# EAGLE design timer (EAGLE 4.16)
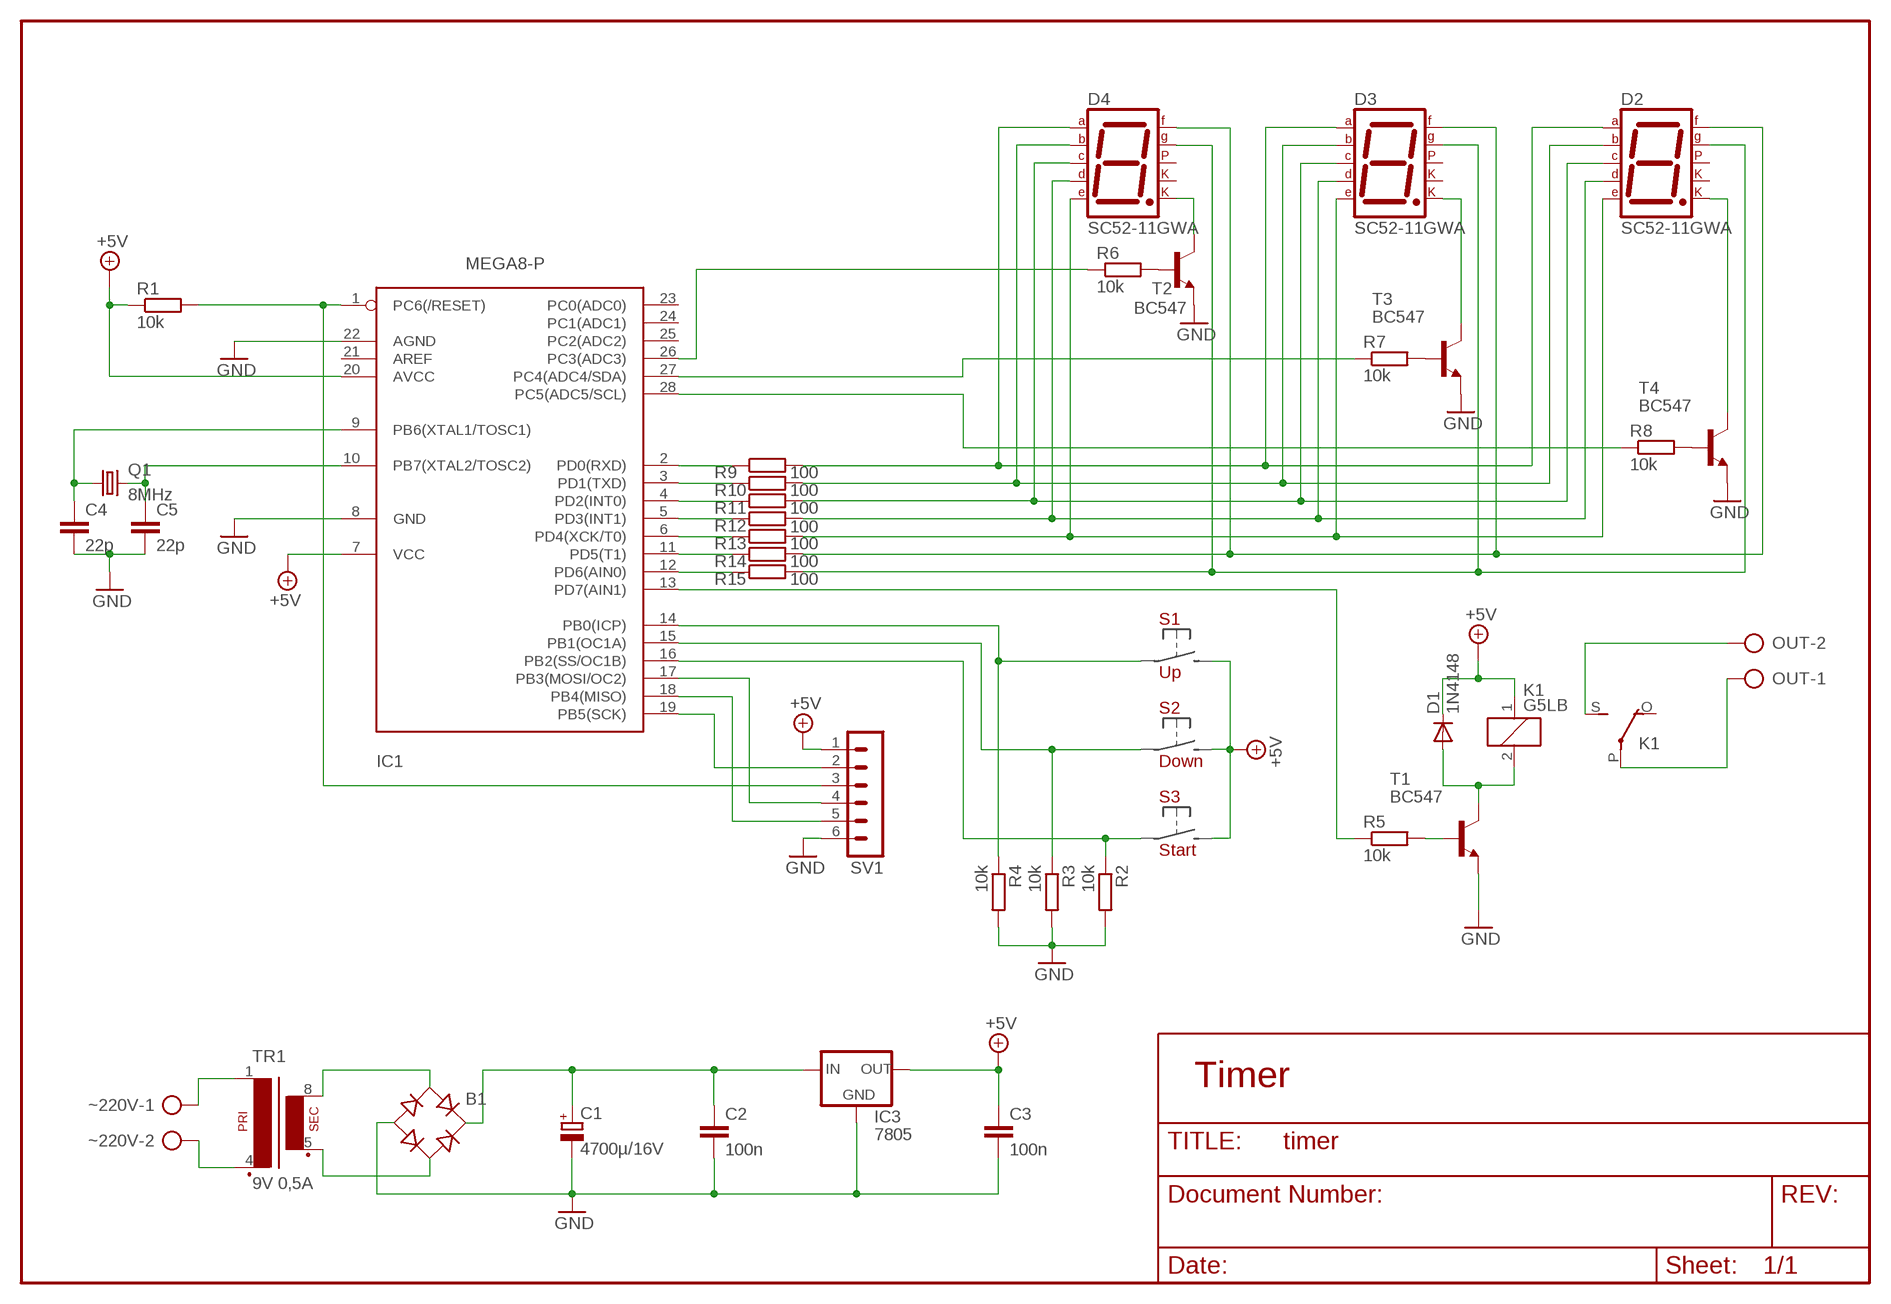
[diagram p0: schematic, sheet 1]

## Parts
B1  RB1A  [RB1A]
C1  4700µ/16V  CPOL-EUE7.5-16  [E7,5-16]
C2  100n  C-EU050-025X075  [C050-025X075]
C3  100n  C-EU050-025X075  [C050-025X075]
C4  22p  C-EU025-025X050  [C025-025X050]
C5  22p  C-EU025-025X050  [C025-025X050]
D1  1N4148  [DO35-10]
D2  SC52-11GWA  7SEG-CK  [7SEG-13]
D3  SC52-11GWA  7SEG-CK  [7SEG-13]
D4  SC52-11GWA  7SEG-CK  [7SEG-13]
IC1  MEGA8-P  [DIL28-3]
IC3  7805  78XXS  [78XXS]
K1  G5LB  G5L  [G5LE]
OUT  AK500/2  [AK500/2]
Q1  8MHz  CRYTALHC49U-V  [HC49U-V]
R1  10k  R-EU_0207/10  [0207/10]
R2  10k  R-EU_0207/10  [0207/10]
R3  10k  R-EU_0207/10  [0207/10]
R4  10k  R-EU_0207/10  [0207/10]
R5  10k  R-EU_0207/10  [0207/10]
R6  10k  R-EU_0207/10  [0207/10]
R7  10k  R-EU_0207/10  [0207/10]
R8  10k  R-EU_0207/10  [0207/10]
R9  100  R-EU_0207/10  [0207/10]
R10  100  R-EU_0207/10  [0207/10]
R11  100  R-EU_0207/10  [0207/10]
R12  100  R-EU_0207/10  [0207/10]
R13  100  R-EU_0207/10  [0207/10]
R14  100  R-EU_0207/10  [0207/10]
R15  100  R-EU_0207/10  [0207/10]
S1  Up  TASTER  [KEY]
S2  Down  TASTER  [KEY]
S3  Start  TASTER  [KEY]
SV1  MA06-1  [MA06-1]
T1  BC547  [TO92]
T2  BC547  [TO92]
T3  BC547  [TO92]
T4  BC547  [TO92]
TR1  9V 0,5A  TR  [TR]
~220V  AK500/2  [AK500/2]

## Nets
+5V: C3.1 D1.C IC1.7(VCC) IC1.20(AVCC) IC3.OUT K1.1 R1.1 S1.2 S2.2 S3.2 SV1.1
GND: B1.- C1.- C2.2 C3.2 C4.2 C5.2 IC1.8(GND) IC1.22(AGND) IC3.GND R2.2 R3.2 R4.2 SV1.6 T1.1(E) T2.1(E) T3.1(E) T4.1(E)
N$1: TR1.1 ~220V.1
N$2: TR1.4 ~220V.2
N$3: B1.AC1 TR1.8
N$4: B1.AC2 TR1.5
N$5: C4.1 IC1.9(PB6(XTAL1/TOSC1)) Q1.1
N$6: B1.+ C1.+ C2.1 IC3.IN
N$7: C5.1 IC1.10(PB7(XTAL2/TOSC2)) Q1.2
N$8: IC1.1(PC6(/RESET)) R1.2 SV1.3
N$9: D2.7(A) D3.7(A) D4.7(A) R9.2
N$10: IC1.19(PB5(SCK)) SV1.2
N$11: IC1.17(PB3(MOSI/OC2)) SV1.4
N$12: IC1.18(PB4(MISO)) SV1.5
N$13: D2.6(B) D3.6(B) D4.6(B) R10.2
N$14: D2.4(C) D3.4(C) D4.4(C) R11.2
N$15: D2.2(D) D3.2(D) D4.2(D) R12.2
N$16: D2.1(E) D3.1(E) D4.1(E) R13.2
N$17: D2.10(G) D3.10(G) D4.10(G) R15.2
N$18: D2.9(F) D3.9(F) D4.9(F) R14.2
N$19: R6.2 T2.2(B)
N$20: R7.2 T3.2(B)
N$21: R8.2 T4.2(B)
N$26: IC1.14(PB0(ICP)) R4.1 S1.1
N$27: IC1.15(PB1(OC1A)) R3.1 S2.1
N$28: IC1.16(PB2(SS/OC1B)) R2.1 S3.1
N$29: K1.S(2:S) OUT.2
N$30: K1.P(2:P) OUT.1
N$31: IC1.13(PD7(AIN1)) R5.1
N$32: R5.2 T1.2(B)
N$33: D1.A K1.2 T1.3(C)
N$59: D4.8(CK2) T2.3(C)
N$60: D3.8(CK2) T3.3(C)
N$61: D2.8(CK2) T4.3(C)
N$62: IC1.26(PC3(ADC3)) R6.1
N$63: IC1.27(PC4(ADC4/SDA)) R7.1
N$64: IC1.28(PC5(ADC5/SCL)) R8.1
N$65: IC1.2(PD0(RXD)) R9.1
N$66: IC1.3(PD1(TXD)) R10.1
N$67: IC1.4(PD2(INT0)) R11.1
N$68: IC1.5(PD3(INT1)) R12.1
N$69: IC1.6(PD4(XCK/T0)) R13.1
N$70: IC1.11(PD5(T1)) R14.1
N$71: IC1.12(PD6(AIN0)) R15.1
Unconnected: D2.3(CK1) D2.5(DP) D3.3(CK1) D3.5(DP) D4.3(CK1) D4.5(DP) IC1.21(AREF) IC1.23(PC0(ADC0)) IC1.24(PC1(ADC1)) IC1.25(PC2(ADC2)) K1.O(2:O)

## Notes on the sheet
- Timer

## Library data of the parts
B1 = rectifier:RB1A: RECTIFIER 1 A
C1 = rcl:CPOL-EU: POLARIZED CAPACITOR, European symbol
C2-C5 = rcl:C-EU: CAPACITOR, European symbol
D1 = diode:1N4148: DIODE
D2-D4 = special:7SEG-CK: 7-segment DISPLAY single cathode, 13 mm
IC1 = atmel:MEGA8-P: MICROCONTROLLER 8 Kbytes FLASH 1 kbytes SRAM 512 bytes EEPROM USART 4-channel 10 bit ADC 2-channel 8 bit ADC Source: avr.lbr
IC3 = v-reg:78XXS: VOLTAGE REGULATOR
K1 = relay:G5L: RELAY 1 x switch, 10 A/120 V AC, 8 A/30 V ADC, Omron
OUT ~220V = con-ptr500:AK500/2: CONNECTOR
Q1 = crystal:CRYTAL: CRYSTAL
R1-R15 = rcl:R-EU_: RESISTOR, European symbol
S1-S3 = 0_my_lib:TASTER
SV1 = con-lstb:MA06-1: PIN HEADER
T1-T4 = transistor:BC547: NPN TRANSISTOR
TR1 = 0_my_lib:TR

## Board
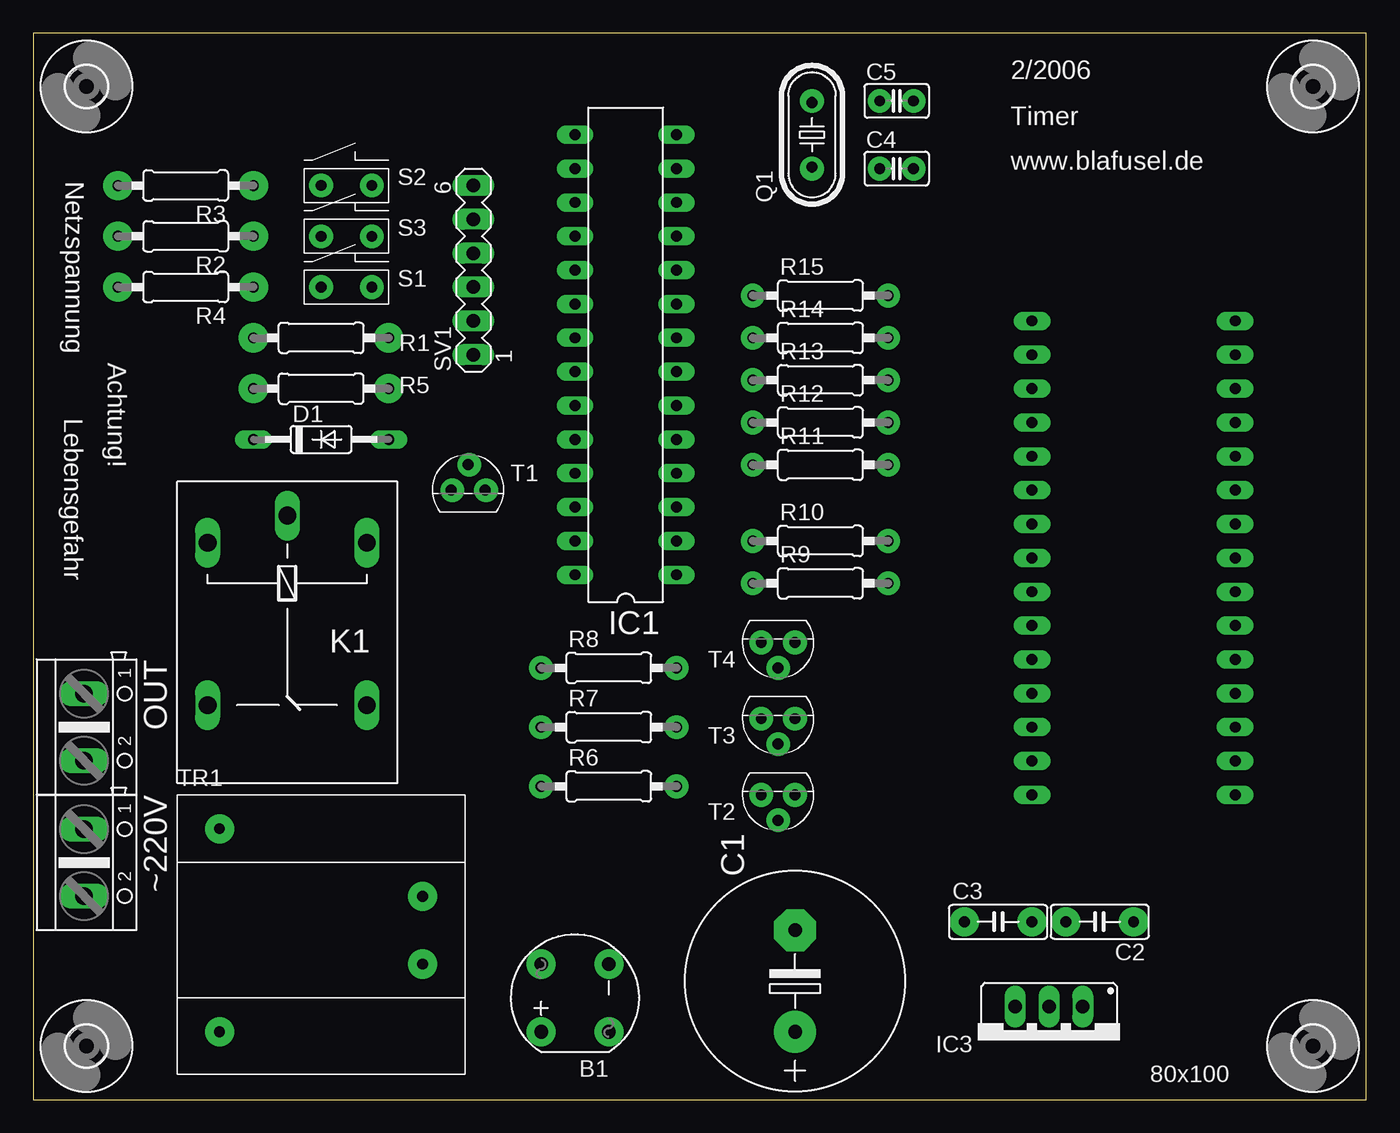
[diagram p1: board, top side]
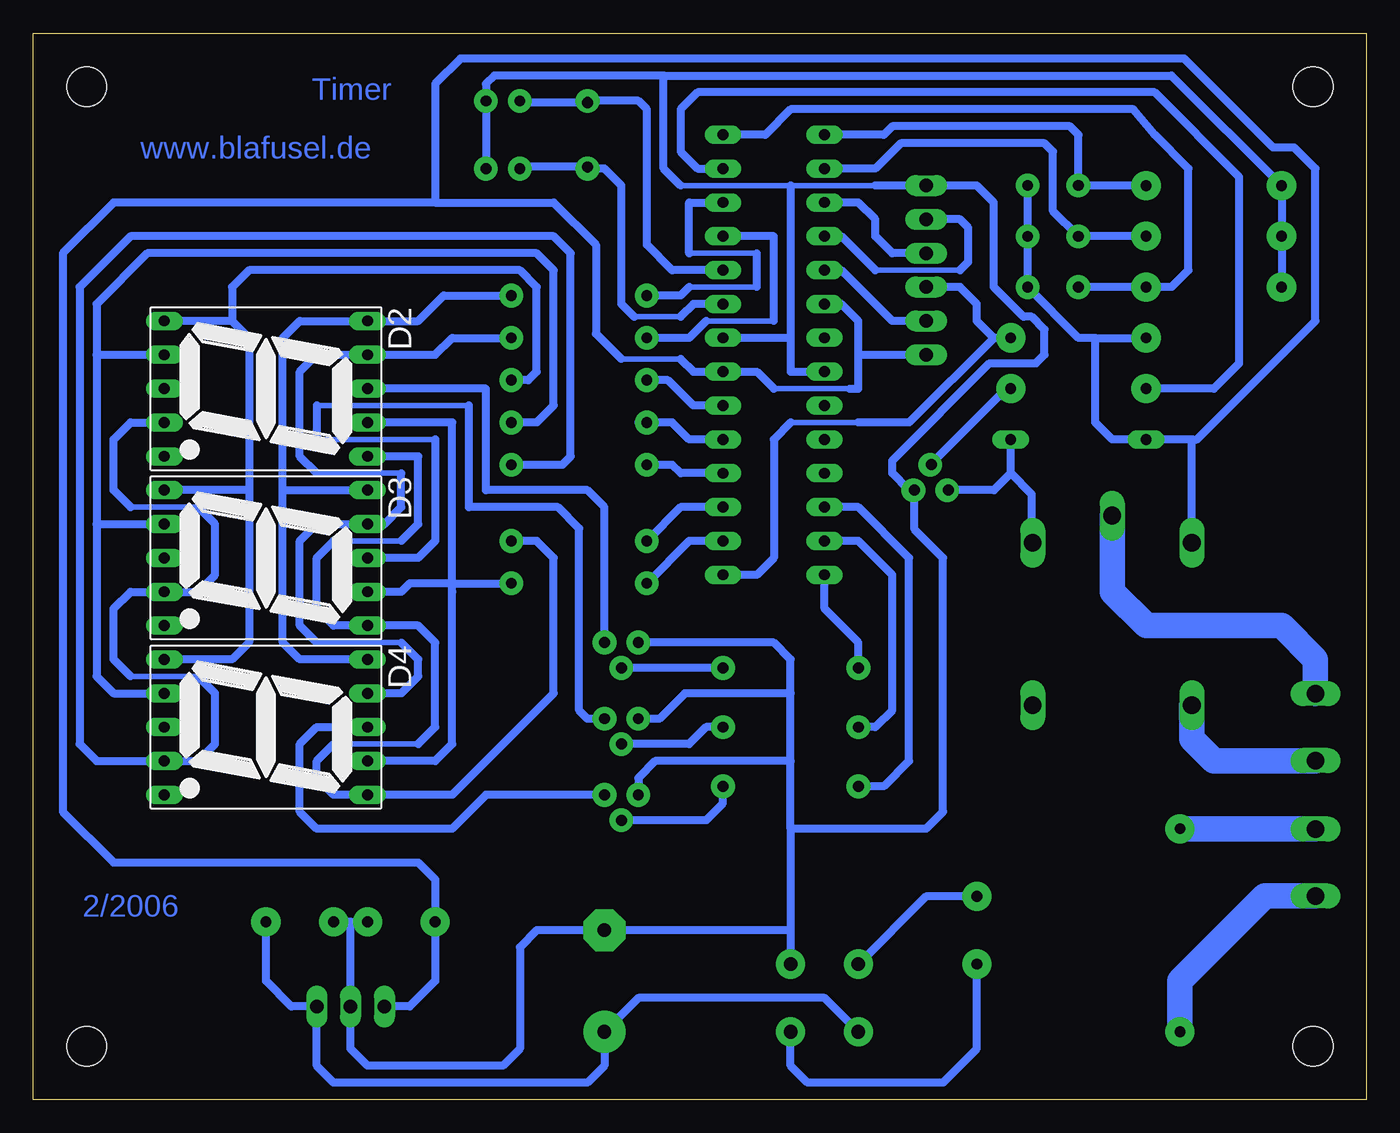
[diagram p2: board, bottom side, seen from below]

Size 100 x 80 mm. Coordinates in mm from the lower left corner, seen from the top.
Outline: 0,0 100,0 100,80 0,80 0,0
Copper layers (1*16): Top 0.035mm / dielectric 1.5mm / Bottom 0.035mm
Design rules "default": minimum track width 10mil, minimum drill 24mil, track to track 8mil, track to pad 8mil, pad to pad 8mil, via to via 8mil, smd to smd 8mil, copper to edge 40mil, drill to drill 8mil, minimum pad ring 11mil, minimum via ring 8mil, stop-mask expansion 4mil, vias tented up to drill 0mil, thermal gap 10mil

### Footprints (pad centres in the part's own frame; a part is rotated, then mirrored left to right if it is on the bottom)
RB1A = drill 1.016 round: + -2.54,2.54 | drill 1.016 octagon: - 2.54,-2.54; AC1 2.54,2.54; AC2 -2.54,-2.54
E7,5-16 = drill 1.016 pad 3.15 round: + -3.81,0 | drill 1.016 pad 3.15 octagon: - 3.81,0
C050-025X075 = drill 0.813 octagon: 1 -2.54,0; 2 2.54,0
C025-025X050 = drill 0.813 octagon: 1 -1.27,0; 2 1.27,0
DO35-10 = drill 0.813 long: A 5.08,0; C -5.08,0
7SEG-13 = drill 0.813 long: 1 -5.08,-7.62; 2 -2.54,-7.62; 3 0,-7.62; 4 2.54,-7.62; 5 5.08,-7.62; 6 5.08,7.62; 7 2.54,7.62; 8 0,7.62; 9 -2.54,7.62; 10 -5.08,7.62
DIL28-3 = drill 0.813 long: 1 -16.51,-3.81; 2 -13.97,-3.81; 3 -11.43,-3.81; 4 -8.89,-3.81; 5 -6.35,-3.81; 6 -3.81,-3.81; 7 -1.27,-3.81; 8 1.27,-3.81; 9 3.81,-3.81; 10 6.35,-3.81; 11 8.89,-3.81; 12 11.43,-3.81; 13 13.97,-3.81; 14 16.51,-3.81; 15 16.51,3.81; 16 13.97,3.81; 17 11.43,3.81; 18 8.89,3.81; 19 6.35,3.81; 20 3.81,3.81; 21 1.27,3.81; 22 -1.27,3.81; 23 -3.81,3.81; 24 -6.35,3.81; 25 -8.89,3.81; 26 -11.43,3.81; 27 -13.97,3.81; 28 -16.51,3.81
78XXS = drill 1.016 long: GND 0,-2.54; IN -2.54,-2.54; OUT 2.54,-2.54
G5LE = drill 1.321 long: 1 -7.493,-5.969; 2 -7.493,5.969; O 4.699,5.969; P -9.525,0; S 4.699,-5.969
AK500/2 = drill 1.321 long: 1 -2.515,0; 2 2.515,0
HC49U-V = drill 0.813 round: 1 -2.413,0; 2 2.413,0
0207/10 = drill 0.813 octagon: 1 -5.08,0; 2 5.08,0
KEY = drill 0.8 pad 1.778 round: 1 1.27,-1.27; 2 5.08,-1.27
MA06-1 = drill 1.016 long: 1 -6.35,0; 2 -3.81,0; 3 -1.27,0; 4 1.27,0; 5 3.81,0; 6 6.35,0
TO92 = drill 0.813 octagon: 1 1.27,0; 2 0,1.905; 3 -1.27,0
TR = drill 0.8 pad 2.184 round: 1 -11.43,7.62; 4 -11.43,-7.62; 5 3.81,-2.54; 8 3.81,2.54
3,0 = hole 3: 0,0

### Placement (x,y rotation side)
B1  40.64,7.62 90 top
C1  57.15,8.89 90 top
C2  80.01,13.34 180 top
C3  72.39,13.34 0 top
C4  64.77,69.85 0 top
C5  64.77,74.93 0 top
D1  21.59,49.53 0 top
D2  82.55,53.34 270 bottom
D3  82.55,40.64 270 bottom
D4  82.55,27.94 270 bottom
IC1  44.45,55.88 90 top
IC3  76.2,4.45 180 top
K1  19.05,34.29 270 top
OUT  3.81,27.94 270 top
Q1  58.42,72.39 90 top
R1  21.59,57.15 0 top
R2  11.43,64.77 180 top
R3  11.43,68.58 180 top
R4  11.43,60.96 180 top
R5  21.59,53.34 0 top
R6  43.18,23.5 0 top
R7  43.18,27.94 0 top
R8  43.18,32.38 0 top
R9  59.05,38.73 0 top
R10  59.05,41.91 0 top
R11  59.05,47.62 0 top
R12  59.05,50.8 0 top
R13  59.05,53.98 0 top
R14  59.05,57.15 0 top
R15  59.05,60.33 0 top
S1  20.32,62.23 0 top
S2  20.32,69.85 0 top
S3  20.32,66.04 0 top
SV1  33.02,62.23 90 top
T1  32.62,45.73 0 top
T2  55.88,22.86 180 top
T3  55.88,28.57 180 top
T4  55.88,34.29 180 top
TR1  25.4,12.7 0 top
U$1  [3,0]  96,4 0 top
U$2  [3,0]  96,76 0 top
U$3  [3,0]  4,4 0 top
U$4  [3,0]  4,76 0 top
~220V  3.81,17.78 270 top

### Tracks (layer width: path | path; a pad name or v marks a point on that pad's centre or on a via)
+5V
  Bottom 0.406: 44.45,53.34 38.73,53.34 | 55.88,55.56 51.44,55.56
  Bottom 0.61: IC1.20 39.37,59.69 38.1,58.42 38.1,55.88 | 44.45,53.34 45.72,54.61 IC1.7 50.48,54.61 51.44,55.56 | D1.C 16.32,49.72 | 38.73,53.34 38.1,53.34 38.1,55.88 | S2.2 S3.2 S1.2 21.59,57.15 20.32,57.15 | 13.02,49.53 12.7,49.53 3.81,58.42 3.81,69.85 5.4,71.44 6.99,71.44 13.65,78.11 67.94,78.11 69.85,76.2 69.85,67.31 | 13.02,49.53 D1.C | IC3.OUT 71.75,6.99 69.85,8.89 C3.1 69.85,16.51 71.12,17.78 93.98,17.78 97.79,21.59 97.79,63.5 93.98,67.31 69.85,67.31 | 38.1,55.88 SV1.1 | 20.32,57.15 R1.1 | D1.C 19.05,49.53 20.32,50.8 20.32,57.15 | 69.85,67.31 60.96,67.31 57.78,64.14 57.78,57.47 55.88,55.56 | K1.1 13.08,49.47 13.02,49.53
GND
  Bottom 0.254: 76.2,6.35 IC3.GND
  Bottom 0.406: 36.83,68.58 43.18,68.58 51.44,68.58
  Bottom 0.61: IC1.22 43.18,54.61 43.18,57.15 | 43.18,57.15 IC1.8 | 51.44,68.58 52.7,69.85 52.7,76.83 53.02,76.83 | 53.02,76.83 14.61,76.83 R3.2 R2.2 R4.2 | 76.2,6.35 76.2,3.81 74.93,2.54 64.77,2.54 63.5,3.81 63.5,11.43 62.23,12.7 C1.- 43.18,12.7 | 76.2,13.34 C3.2 | 76.2,13.34 C2.2 | IC3.GND 76.2,13.34 | 43.18,12.7 B1.- | 43.18,20.32 43.18,12.7 | 43.18,20.32 43.18,25.4 | 43.18,25.4 43.18,30.48 | 43.18,30.48 43.18,33.02 44.45,34.29 T4.1 | 43.18,20.32 33.02,20.32 31.75,21.59 31.75,40.64 33.89,42.78 T1.1 34.3,45.73 35.56,46.99 35.56,47.94 28.26,55.24 24.77,55.24 24.13,55.88 24.13,57.78 25.08,58.74 25.72,58.74 27.94,60.96 27.94,67.31 29.21,68.58 SV1.6 36.83,68.58 | T3.1 53.02,28.57 51.12,30.48 43.18,30.48 | T2.1 54.61,24.13 53.34,25.4 43.18,25.4 | C4.2 C5.2 66.04,76.2 65.41,76.83 53.02,76.83 | 43.18,68.58 43.18,57.15
N$1
  Bottom 1.27: 13.95,20.3 TR1.1
  Bottom 1.93: ~220V.1 13.95,20.3
N$2
  Bottom 1.93: ~220V.2 7.59,15.27 13.97,8.89 TR1.4
N$3
  Bottom 0.61: TR1.8 33.02,15.24 B1.AC1
N$4
  Bottom 0.61: TR1.5 29.21,3.81 31.75,1.27 41.91,1.27 43.18,2.54 B1.AC2
N$5
  Bottom 0.406: 51.44,58.74 54.93,58.74
  Bottom 0.61: IC1.9 50.48,59.69 51.44,58.74 | 54.93,58.74 55.88,59.69 55.88,68.58 57.15,69.85 58.42,69.85 Q1.1 63.37,69.98 C4.1
N$6
  Bottom 0.61: B1.+ 40.64,7.62 54.61,7.62 C1.+ 57.15,2.54 58.42,1.27 77.47,1.27 78.74,2.54 IC3.IN 80.64,6.99 82.55,8.89 C2.1
N$7
  Bottom 0.61: IC1.10 52.07,62.23 53.98,64.14 53.98,74.3 54.61,74.93 58.42,74.93 Q1.2 63.37,74.8 C5.1
N$8
  Bottom 0.406: 38.1,50.8 43.18,50.8
  Bottom 0.61: IC1.1 45.72,39.37 44.45,40.64 44.45,49.53 43.18,50.8 | SV1.3 30.48,60.96 29.21,59.69 29.21,58.42 27.94,57.15 | R1.2 27.94,57.15 | 38.1,50.8 34.29,50.8 27.94,57.15
N$9
  Bottom 0.61: 68.58,38.73 R9.2 | 68.58,38.73 71.75,38.73 72.39,38.1 D3.7 | D4.7 69.85,25.4 68.58,26.67 68.58,38.1 | 68.58,38.1 68.58,38.73 | D2.7 68.58,50.8 68.58,38.1
N$10
  Bottom 0.61: SV1.2 35.56,58.42 39.37,62.23 IC1.19
N$11
  Bottom 0.61: IC1.17 38.1,67.31 36.83,66.04 36.83,64.77 35.56,63.5 SV1.4
N$12
  Bottom 0.406: 30.48,62.23 36.83,62.23
  Bottom 0.61: IC1.18 39.37,64.77 36.83,62.23 | SV1.5 30.48,66.04 29.84,65.41 29.84,62.87 30.48,62.23
N$13
  Bottom 0.406: 77.47,26.67 71.12,26.67 | 77.47,41.91 72.39,41.91
  Bottom 0.61: 77.47,26.67 78.74,25.4 78.74,24.13 77.47,22.86 D4.6 68.58,22.86 60.96,30.48 60.96,40.64 62.23,41.91 R10.2 | 71.12,26.67 69.85,27.94 69.85,34.29 71.12,35.56 D3.6 77.47,35.56 78.74,36.83 78.74,40.64 77.47,41.91 | 72.39,41.91 71.12,43.18 71.12,48.26 D2.6
N$14
  Bottom 0.406: 87.63,44.45 92.71,44.45 | 87.63,31.75 92.71,31.75
  Bottom 0.61: D2.4 92.71,50.8 93.98,49.53 93.98,45.72 92.71,44.45 | 87.63,44.45 86.36,43.18 86.36,39.37 87.63,38.1 D3.4 92.71,38.1 93.98,36.83 93.98,33.02 92.71,31.75 | 87.63,31.75 86.36,30.48 86.36,26.67 87.63,25.4 D4.4 95.25,25.4 96.52,26.67 96.52,60.96 92.71,64.77 60.96,64.77 59.69,63.5 59.69,48.26 60.33,47.62 R11.2
N$15
  Bottom 0.61: 95.25,55.88 95.25,59.69 91.44,63.5 62.23,63.5 60.96,62.23 60.96,52.07 62.23,50.8 R12.2 | 88.9,30.48 D4.2 93.98,30.48 95.25,31.75 95.25,43.18 | 95.25,55.88 95.25,43.18 | 95.25,43.18 D3.2 | 95.25,55.88 D2.2
N$16
  Bottom 0.61: 85.09,58.42 D2.1 | 85.09,58.42 83.82,57.15 83.82,45.72 | 83.82,45.72 83.82,34.29 85.09,33.02 D4.1 | 83.82,45.72 D3.1 | R13.2 62.87,53.98 62.23,54.61 62.23,60.96 63.5,62.23 83.82,62.23 85.09,60.96 85.09,58.42
N$17
  Bottom 0.61: R15.2 69.22,60.33 71.12,58.42 D2.10 80.01,58.42 81.28,57.15 81.28,45.72 | 81.28,45.72 81.28,34.29 80.01,33.02 D4.10 | 81.28,45.72 D3.10
N$18
  Bottom 0.406: 72.39,46.99 78.74,46.99 | 72.39,34.29 78.74,34.29
  Bottom 0.61: R14.2 68.58,57.15 69.85,55.88 D2.9 78.74,55.88 80.01,54.61 80.01,48.26 78.74,46.99 | 72.39,46.99 72.39,44.45 73.66,43.18 D3.9 78.74,43.18 80.01,41.91 80.01,35.56 78.74,34.29 | 72.39,34.29 71.12,33.02 71.12,31.75 72.39,30.48 D4.9
N$19
  Bottom 0.61: R6.2 48.26,22.23 49.53,20.95 T2.2
N$20
  Bottom 0.61: R7.2 49.53,27.94 50.8,26.67 T3.2
N$21
  Bottom 0.61: T4.2 55.88,32.7 55.56,32.38 R8.2
N$22  (via drill 0.6 pad 2.18)
  other vias: 82.55,13.34
N$23  (via drill 0.6 pad 2.18)
  other vias: 77.47,13.34
N$24  (via drill 0.6 pad 2.18)
  other vias: 74.93,13.34
N$25  (via drill 0.6 pad 1.78)
  other vias: 58.42,69.85
N$26
  Bottom 0.61: IC1.14 45.09,72.39 43.18,74.3 17.46,74.3 15.88,72.39 13.34,69.85 13.34,62.23 14.61,60.96 R4.1 S1.1
N$27
  Bottom 0.61: IC1.15 36.2,72.39 35.56,73.03 22.23,73.03 21.59,72.39 S2.1 R3.1
N$28
  Bottom 0.61: IC1.16 36.83,69.85 34.92,71.75 24.13,71.75 23.5,71.12 23.5,66.67 S3.1 R2.1
N$29
  Bottom 1.27: OUT.2 3.81,25.4
  Bottom 1.93: K1.S 13.08,27.05 11.43,25.4 3.81,25.4
N$30
  Bottom 1.93: K1.P 19.05,38.1 16.51,35.56 6.35,35.56 3.81,33.02 OUT.1
N$31
  Bottom 0.61: IC1.13 50.16,69.85 51.44,71.12 51.44,74.3 50.16,75.56 15.88,75.56 9.53,69.22 9.53,55.24 11.43,53.34 R5.1
N$32
  Bottom 0.61: 32.69,47.63 32.7,47.62 | T1.2 32.69,47.63 | R5.2 26.99,53.34 32.69,47.63
N$33
  Bottom 0.61: 26.67,46.99 D1.A | 26.67,46.99 25.08,45.4 25.08,41.59 25.02,41.66 K1.2 | T1.3 27.93,45.73 26.67,46.99
N$34  (via drill 0.6 pad 1.78)
  other vias: 58.42,74.93
N$35  (via drill 0.6 pad 1.78)
  other vias: 63.5,74.93
N$36  (via drill 0.6 pad 1.78)
  other vias: 66.04,74.93
N$37  (via drill 0.6 pad 1.78)
  other vias: 31.43,45.72
N$38  (via drill 0.6 pad 1.78)
  other vias: 33.97,45.72
N$39  (via drill 0.6 pad 1.78)
  other vias: 32.7,47.62
N$40  (via drill 0.6 pad 2.18)
  other vias: 16.51,60.96
N$41  (via drill 0.6 pad 2.18)
  other vias: 6.35,60.96
N$42  (via drill 0.6 pad 2.18)
  other vias: 26.67,53.34
N$43  (via drill 0.6 pad 2.18)
  other vias: 6.35,64.77
N$44  (via drill 0.6 pad 2.18)
  other vias: 16.51,64.77
N$45  (via drill 0.6 pad 2.18)
  other vias: 16.51,53.34
N$46  (via drill 0.6 pad 2.18)
  other vias: 16.51,57.15
N$47  (via drill 0.6 pad 2.18)
  other vias: 26.67,57.15
N$48  (via drill 0.6 pad 2.18)
  other vias: 16.51,68.58
N$49  (via drill 0.6 pad 2.18)
  other vias: 6.35,68.58
N$50  (via drill 0.6 pad 2.18)
  other vias: 43.18,10.16
N$51  (via drill 0.6 pad 2.18)
  other vias: 38.1,10.16
N$52  (via drill 0.6 pad 2.18)
  other vias: 43.18,5.08
N$53  (via drill 0.6 pad 2.18)
  other vias: 38.1,5.08
N$54  (via drill 0.6 pad 1.78)
  other vias: 77.47,13.34
N$55  (via drill 0.6 pad 1.78)
  other vias: 82.55,13.34
N$56  (via drill 0.6 pad 1.78)
  other vias: 69.85,13.34
N$57  (via drill 0.6 pad 1.78)
  other vias: 74.93,13.34
N$58  (via drill 0.6 pad 2.18)
  other vias: 69.85,13.34
N$59
  Bottom 0.61: T2.3 66.04,22.86 68.58,20.32 78.74,20.32 80.01,21.59 80.01,26.67 78.74,27.94 D4.8
N$60
  Bottom 0.406: 67.31,52.07 78.74,52.07 | 78.74,49.53 69.85,49.53
  Bottom 0.61: T3.3 58.42,28.57 59.05,29.21 59.05,42.86 60.64,44.45 67.31,44.45 67.31,52.07 | 78.74,52.07 78.74,49.53 | 69.85,49.53 69.85,41.91 71.12,40.64 D3.8
N$61
  Bottom 0.61: T4.3 57.15,44.45 58.42,45.72 66.04,45.72 66.04,53.34 D2.8
N$62
  Bottom 0.61: IC1.26 38.1,44.45 34.29,40.64 34.29,25.4 36.2,23.5 R6.1
N$63
  Bottom 0.61: R7.1 36.83,27.94 35.56,29.21 35.56,39.37 38.1,41.91 IC1.27
N$64
  Bottom 0.61: IC1.28 40.64,36.83 38.1,34.29 R8.1
N$65
  Bottom 0.61: IC1.2 50.8,41.91 R9.1
N$66
  Bottom 0.61: IC1.3 51.44,44.45 R10.1
N$67
  Bottom 0.61: IC1.4 51.44,46.99 52.07,47.62 R11.1
N$68
  Bottom 0.61: IC1.5 50.8,49.53 52.07,50.8 R12.1 54.61,50.8
N$69
  Bottom 0.61: IC1.6 50.48,52.07 52.39,53.98 R13.1
N$70
  Bottom 0.406: 44.45,58.42 49.53,58.42
  Bottom 0.61: R14.1 50.8,57.15 49.53,58.42 | 44.45,58.42 44.45,64.77 IC1.11
N$71
  Bottom 0.406: 45.72,60.96 50.8,60.96 | 45.72,63.5 50.8,63.5
  Bottom 0.61: R15.1 51.44,60.33 50.8,60.96 | 45.72,60.96 45.72,63.5 | 50.8,63.5 50.8,67.31 IC1.12
N$72  (via drill 0.6 pad 1.78)
  other vias: 63.5,69.85
N$73  (via drill 0.6 pad 1.78)
  other vias: 66.04,69.85
N$74  (via drill 0.6 pad 1.78)
  other vias: 53.98,60.33
N$75  (via drill 0.6 pad 1.78)
  other vias: 64.14,57.15
N$76  (via drill 0.6 pad 1.78)
  other vias: 64.14,47.62
N$77  (via drill 0.6 pad 1.78)
  other vias: 53.98,47.62
N$78  (via drill 0.6 pad 1.78)
  other vias: 64.14,60.33
N$79  (via drill 0.6 pad 1.78)
  other vias: 53.98,50.8
N$80  (via drill 0.6 pad 1.78)
  other vias: 64.14,53.98
N$81  (via drill 0.6 pad 1.78)
  other vias: 64.14,50.8
N$82  (via drill 0.6 pad 1.78)
  other vias: 53.98,38.73
N$83  (via drill 0.6 pad 1.78)
  other vias: 53.98,57.15
N$84  (via drill 0.6 pad 1.78)
  other vias: 53.98,53.98
N$85  (via drill 0.6 pad 1.78)
  other vias: 38.1,32.38
N$86  (via drill 0.6 pad 1.78)
  other vias: 64.14,38.73
N$87  (via drill 0.6 pad 1.78)
  other vias: 64.14,41.91
N$88  (via drill 0.6 pad 1.78)
  other vias: 48.26,32.38
N$89  (via drill 0.6 pad 1.78)
  other vias: 53.98,41.91
N$90  (via drill 0.6 pad 1.78)
  other vias: 38.1,27.94
N$91  (via drill 0.6 pad 1.78)
  other vias: 48.26,23.5
N$92  (via drill 0.6 pad 1.78)
  other vias: 48.26,27.94
N$93  (via drill 0.6 pad 1.78)
  other vias: 38.1,23.5
N$94  (via drill 0.6 pad 1.78)
  other vias: 55.88,20.95
N$95  (via drill 0.6 pad 1.78)
  other vias: 57.15,22.86
N$96  (via drill 0.6 pad 1.78)
  other vias: 54.61,22.86
N$97  (via drill 0.6 pad 1.78)
  other vias: 54.61,28.57
N$98  (via drill 0.6 pad 1.78)
  other vias: 57.15,28.57
N$99  (via drill 0.6 pad 1.78)
  other vias: 54.61,34.29
N$100  (via drill 0.6 pad 1.78)
  other vias: 55.88,32.38
N$101  (via drill 0.6 pad 1.78)
  other vias: 57.15,34.29
N$102  (via drill 0.6 pad 1.78)
  other vias: 55.88,26.67
N$103  (via drill 0.6 pad 1.78)
  other vias: 96,76
N$104  (via drill 0.6 pad 1.78)
  other vias: 96,4
N$105  (via drill 0.6 pad 1.78)
  other vias: 4,4
N$106  (via drill 0.6 pad 1.78)
  other vias: 4,76

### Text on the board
Bottom: Timer | www.blafusel.de | 2/2006
tNames: 2/2006 | Timer | www.blafusel.de | Netzspannung | Achtung! | Lebensgefahr | 80x100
